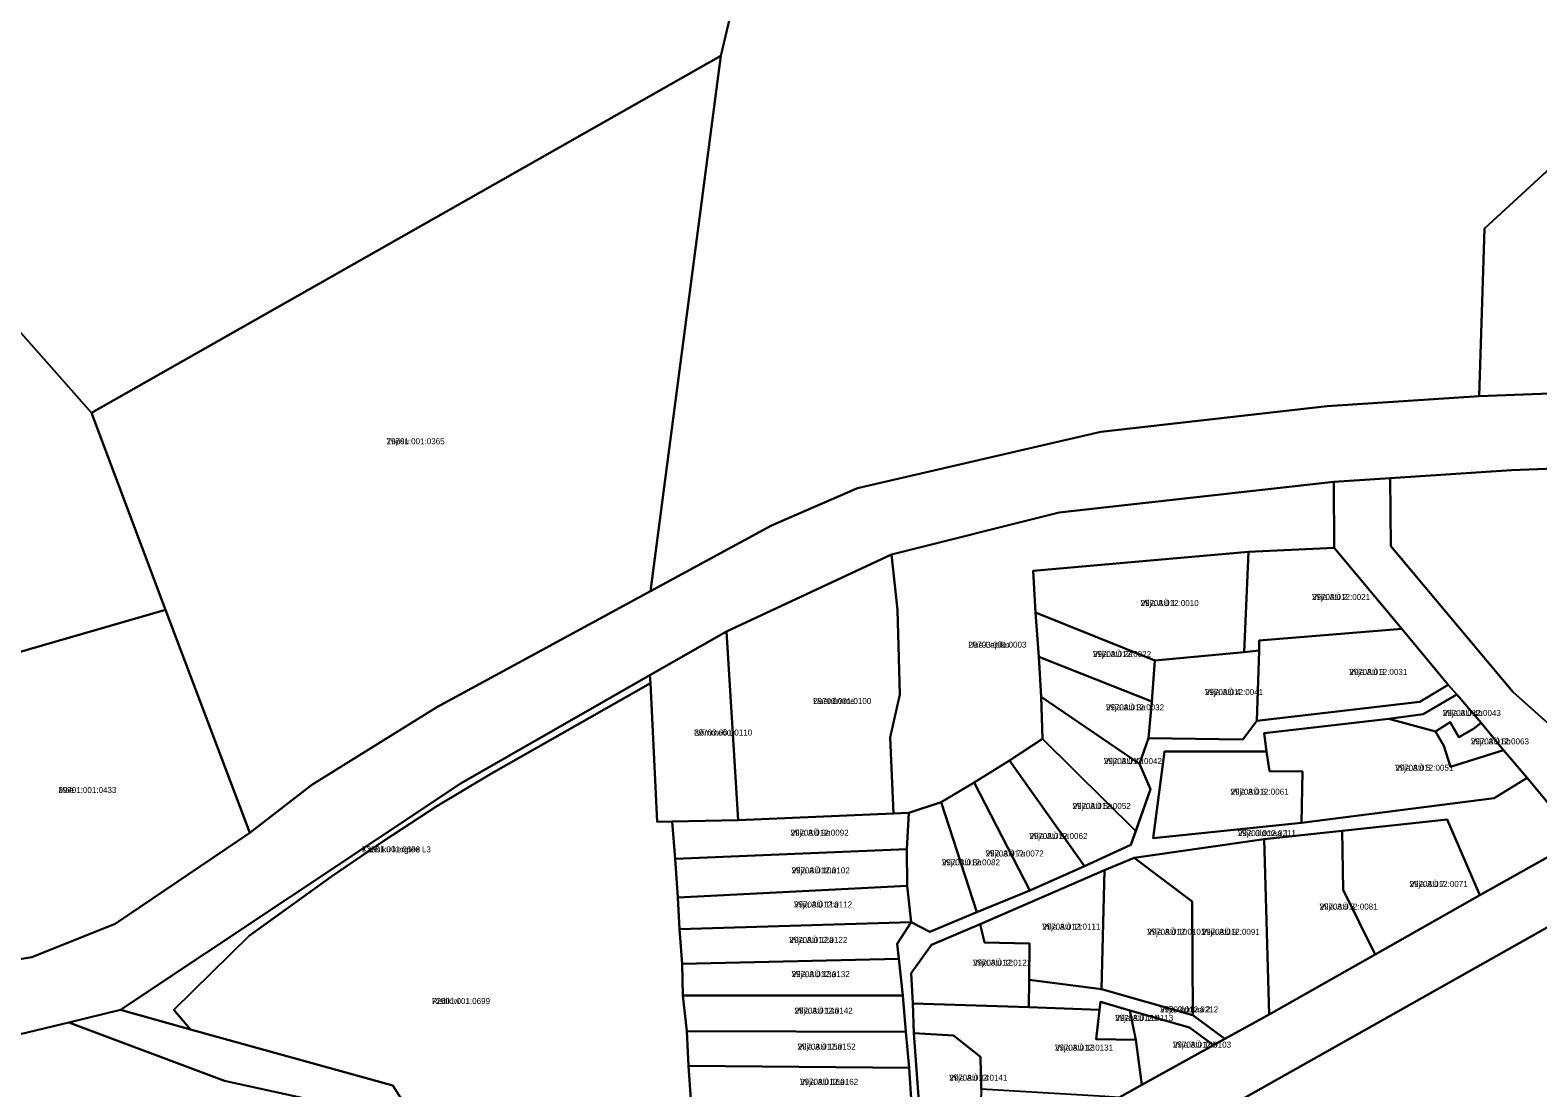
# Model space of a CAD drawing. Extents: x 504287 to 537970, y 6539941 to 6586214.
# Drawn here: x 518594.6 to 518970.8, y 6562077.4 to 6562341.2 of the extents above; entities that cross this region are included whole.
import ezdxf

# ---------------------------------------------------------------- set-up
doc = ezdxf.new("R2010")
doc.units = 0
for name, color, linetype in [('L_AADRESS', 7, 'Continuous'), ('PIIR', 7, 'Continuous'), ('TUNNUS', 7, 'Continuous')]:
    doc.layers.add(name, color=color, linetype=linetype)

msp = doc.modelspace()

# ---------------------------------------------------------------- linework, layer by layer
at = {"layer": 'PIIR'}
for points in [[(518475.75, 6562758.01), (518677.1, 6562981.81), (518635.19, 6562690.91), (518826.94, 6562587.62), (518766.99, 6562334.8), (518609.92, 6562245.71), (518524.03, 6562342.9), (518469.95, 6562404.01), (518435.56, 6562442.92), (518449.9, 6562487.21), (518389.7, 6562505.8), (518316.62, 6562566.33)], [(518766.99, 6562334.8), (518749.42, 6562201.27), (518696.14, 6562172.35), (518664.92, 6562152.99), (518649.43, 6562140.98), (518628.39, 6562196.62), (518609.92, 6562245.71)], [(518991.5, 6562322.94), (519036.8, 6562302.12), (519020.18, 6562252.3), (518956.2, 6562249.85), (518957.55, 6562291.71)], [(518933.96, 6562229.44), (518964.27, 6562231.47), (519024.63, 6562233.72), (519022.07, 6562169.2), (518984.95, 6562157.97), (518964.56, 6562176.11), (518934.17, 6562212.46)], [(518919.99, 6562212.04), (518898.62, 6562211.09), (518844.91, 6562206.29), (518845.46, 6562195.91), (518846.34, 6562184.88), (518846.86, 6562174.89), (518847.25, 6562164.44), (518838.96, 6562159.05), (518830.2, 6562153.55), (518821.98, 6562148.63), (518813.91, 6562145.98), (518810.05, 6562145.81), (518809.18, 6562164.75), (518811.64, 6562175.46), (518811.01, 6562196.57), (518809.58, 6562210.38), (518851.41, 6562220.9), (518919.96, 6562228.5)], [(518845.46, 6562195.91), (518844.91, 6562206.29), (518898.62, 6562211.09), (518897.52, 6562186.06), (518875.27, 6562183.98)], [(518901.28, 6562186.44), (518897.52, 6562186.06), (518898.62, 6562211.09), (518919.99, 6562212.04), (518936.93, 6562191.82), (518901.32, 6562188.99)], [(518811.01, 6562196.57), (518811.64, 6562175.46), (518809.18, 6562164.75), (518810.05, 6562145.81), (518771.31, 6562144.14), (518768.38, 6562191.22), (518809.58, 6562210.38)], [(518566.68, 6562105.2), (518552.93, 6562174.78), (518628.39, 6562196.62), (518649.43, 6562140.98), (518615.87, 6562118.26), (518595.02, 6562109.94)], [(518845.46, 6562195.91), (518875.27, 6562183.98), (518874.52, 6562173.73), (518846.34, 6562184.88)], [(518771.31, 6562144.14), (518754.86, 6562143.79), (518751.09, 6562143.74), (518749.4, 6562178.27), (518749.29, 6562180.29), (518768.38, 6562191.22)], [(518901.28, 6562186.44), (518901.32, 6562188.99), (518936.93, 6562191.82), (518948.45, 6562177.91), (518941.35, 6562173.64), (518900.72, 6562168.91)], [(518846.34, 6562184.88), (518874.52, 6562173.73), (518873.68, 6562164.6), (518871.43, 6562158.17), (518846.86, 6562174.89)], [(518874.52, 6562173.73), (518875.27, 6562183.98), (518897.52, 6562186.06), (518901.28, 6562186.44), (518900.72, 6562168.91), (518897.21, 6562164.22), (518873.68, 6562164.6)], [(518634.67, 6562091.94), (518617.21, 6562096.8), (518702.16, 6562153.36), (518749.29, 6562180.29), (518749.4, 6562178.27), (518709.77, 6562155.75), (518696.13, 6562147.63), (518682.85, 6562138.99), (518669.79, 6562130.13), (518649.28, 6562115.28), (518630.51, 6562096.8)], [(518846.86, 6562174.89), (518871.43, 6562158.17), (518874.2, 6562151.83), (518870.52, 6562141.37), (518847.25, 6562164.44)], [(518933.67, 6562169.42), (518942.21, 6562170.56), (518950.6, 6562175.47), (518956.7, 6562168.4), (518954.81, 6562166.94), (518951.1, 6562164.8), (518948.91, 6562168.62), (518945.32, 6562166.26)], [(518912.14, 6562156.29), (518903.88, 6562156.4), (518903.16, 6562161.28), (518902.55, 6562165.87), (518933.67, 6562169.42), (518945.32, 6562166.26), (518947.37, 6562162.71), (518949.05, 6562157.47), (518962.24, 6562161.56), (518968.14, 6562154.66), (518959.89, 6562149.65), (518911.86, 6562143.5)], [(518947.37, 6562162.71), (518945.32, 6562166.26), (518948.91, 6562168.62), (518951.1, 6562164.8), (518954.81, 6562166.94), (518956.7, 6562168.4), (518962.24, 6562161.56), (518949.05, 6562157.47)], [(518847.25, 6562164.44), (518870.52, 6562141.37), (518869.28, 6562137.99), (518857.68, 6562132.7), (518838.96, 6562159.05)], [(518830.2, 6562153.55), (518838.96, 6562159.05), (518857.68, 6562132.7), (518844.08, 6562126.56)], [(518877.68, 6562161.25), (518903.16, 6562161.28), (518903.88, 6562156.4), (518912.14, 6562156.29), (518911.86, 6562143.5), (518874.87, 6562139.68)], [(518821.98, 6562148.63), (518830.2, 6562153.55), (518844.08, 6562126.56), (518830.84, 6562121.22)], [(518814.48, 6562118.73), (518813.49, 6562127.78), (518813.41, 6562136.9), (518813.91, 6562145.98), (518821.98, 6562148.63), (518830.84, 6562121.22), (518819.1, 6562116.28)], [(518813.91, 6562145.98), (518813.41, 6562136.9), (518755.53, 6562134.53), (518754.86, 6562143.79), (518771.31, 6562144.14), (518810.05, 6562145.81)], [(518922.24, 6562126.75), (518922.01, 6562141.47), (518948.22, 6562144.3), (518956.32, 6562125.43), (518930.22, 6562110.67)], [(518884.78, 6562095.5), (518884.6, 6562123.84), (518870.14, 6562134.78), (518902.5, 6562139.4), (518903.75, 6562095.65), (518892.74, 6562089.63)], [(518902.5, 6562139.4), (518922.01, 6562141.47), (518922.24, 6562126.75), (518930.22, 6562110.67), (518903.75, 6562095.65)], [(518755.53, 6562134.53), (518813.41, 6562136.9), (518813.49, 6562127.78), (518756.24, 6562124.83)], [(518844.21, 6562011.8), (518836.84, 6562012.6), (518844.21, 6562037.85), (518845.16, 6562041.36), (518846.09, 6562044.48), (518861.89, 6562072.25), (518862.8, 6562075.26), (518866.38, 6562074.95), (518871.99, 6562078.13), (518889.92, 6562088.02), (518892.74, 6562089.63), (518903.75, 6562095.65), (518930.22, 6562110.67), (518956.32, 6562125.43), (518980.97, 6562139.21), (518990.73, 6562127.26), (518881.96, 6562066.06), (518860.8, 6562045.82), (518853.6, 6562034.04)], [(518862.74, 6562131.66), (518870.14, 6562134.78), (518884.6, 6562123.84), (518884.78, 6562095.5), (518861.94, 6562102.02)], [(518843.95, 6562113.38), (518832.76, 6562113.61), (518831.67, 6562118.23), (518862.74, 6562131.66), (518861.94, 6562102.02), (518843.94, 6562104.34)], [(518756.24, 6562124.83), (518813.49, 6562127.78), (518814.48, 6562118.73), (518756.68, 6562116.93)], [(518882.09, 6561992.35), (518844.21, 6562011.8), (518853.6, 6562034.04), (518860.8, 6562045.82), (518881.96, 6562066.06), (518990.73, 6562127.26), (519021.61, 6562068.59), (518984.83, 6562046.85), (518949.38, 6562025.42), (518930.25, 6562014.02), (518911.77, 6562003.1), (518908.77, 6562008.3)], [(518756.68, 6562116.93), (518814.48, 6562118.73), (518810.96, 6562113.31), (518811.34, 6562109.58), (518757.31, 6562108.33)], [(518814.5, 6562105.99), (518819.51, 6562113.03), (518831.67, 6562118.23), (518832.76, 6562113.61), (518843.95, 6562113.38), (518843.94, 6562104.34), (518843.81, 6562097.48), (518814.9, 6562098.4)], [(518757.31, 6562108.33), (518811.34, 6562109.58), (518812.4, 6562100.41), (518757.52, 6562100.43)], [(518843.94, 6562104.34), (518861.94, 6562102.02), (518884.78, 6562095.5), (518892.74, 6562089.63), (518889.92, 6562088.02), (518883.92, 6562092.44), (518869.02, 6562096.66), (518861.69, 6562098.84), (518861.48, 6562096.87), (518843.81, 6562097.48)], [(518757.52, 6562100.43), (518812.4, 6562100.41), (518813.1, 6562091.32), (518758.46, 6562091.52)], [(518831.8, 6562085.15), (518825, 6562090.41), (518815.14, 6562091.02), (518814.9, 6562098.4), (518843.81, 6562097.48), (518861.48, 6562096.87), (518860.61, 6562089.55), (518870.51, 6562089.33), (518871.99, 6562078.13), (518866.38, 6562074.95), (518862.8, 6562075.26), (518831.94, 6562077.04)], [(518861.48, 6562096.87), (518861.69, 6562098.84), (518869.02, 6562096.66), (518870.51, 6562089.33), (518860.61, 6562089.55)], [(518870.51, 6562089.33), (518869.02, 6562096.66), (518883.92, 6562092.44), (518889.92, 6562088.02), (518871.99, 6562078.13)], [(518643.09, 6562079.14), (518676.15, 6562071.9), (518676.82, 6561797.25), (518631.02, 6561816.34), (518629.22, 6561817.09), (518537.2, 6561858.42), (518545.01, 6561888.17), (518554.72, 6561923.51), (518519.2, 6561922.14), (518469.34, 6561919.09), (518472.12, 6561926.87), (518556.08, 6562085.74), (518577.49, 6562087.27), (518604.29, 6562093.69)], [(518758.46, 6562091.52), (518813.1, 6562091.32), (518814, 6562082.33), (518758.89, 6562082.9)], [(518815.14, 6562091.02), (518825, 6562090.41), (518831.8, 6562085.15), (518831.94, 6562077.04), (518831.85, 6562073.82), (518861.89, 6562072.25), (518853.23, 6562067.33), (518816.66, 6562070.63)], [(518759.51, 6562074.58), (518758.89, 6562082.9), (518814, 6562082.33), (518814.51, 6562073.37)]]:
    msp.add_lwpolyline(points, close=True, dxfattribs=at)
for points in [[(519354.1, 6562777.58), (518991.5, 6562322.94), (518957.55, 6562291.71), (518956.2, 6562249.85), (518918.29, 6562247.42), (518861.76, 6562241), (518801.03, 6562226.96), (518779.6, 6562217.63), (518749.42, 6562201.27), (518766.99, 6562334.8), (518826.94, 6562587.62)], [(518207.35, 6562413.84), (518257.69, 6562495.23), (518422.52, 6562457.55), (518435.56, 6562442.92), (518469.95, 6562404.01), (518427.57, 6562222.45), (518498.13, 6562231.74), (518524.03, 6562342.9), (518609.92, 6562245.71), (518628.39, 6562196.62), (518552.93, 6562174.78), (518488.36, 6562156.01), (518362.48, 6562148.68), (518356.06, 6562086.39), (518343.83, 6562086.7), (518343.82, 6562090.13), (518332.95, 6562090.41), (518334.78, 6562134.39), (518277.98, 6562164.81), (518251.89, 6562177.79), (518220.42, 6562192.89)], [(518566.68, 6562105.2), (518595.02, 6562109.94), (518615.87, 6562118.26), (518649.43, 6562140.98), (518664.92, 6562152.99), (518696.14, 6562172.35), (518749.42, 6562201.27), (518779.6, 6562217.63), (518801.03, 6562226.96), (518861.76, 6562241), (518918.29, 6562247.42), (518956.2, 6562249.85), (519020.18, 6562252.3), (519120.43, 6562250.63), (519226.17, 6562256.12), (519357.09, 6562234.09)], [(519265.7, 6562230.41), (519223.24, 6562237.31), (519117.52, 6562231.81), (519024.63, 6562233.72), (518964.27, 6562231.47), (518933.96, 6562229.44), (518919.96, 6562228.5), (518851.41, 6562220.9), (518809.58, 6562210.38), (518768.38, 6562191.22), (518749.29, 6562180.29), (518702.16, 6562153.36), (518617.21, 6562096.8), (518604.29, 6562093.69), (518577.49, 6562087.27)], [(518980.97, 6562139.21), (518968.14, 6562154.66), (518962.24, 6562161.56), (518956.7, 6562168.4), (518950.6, 6562175.47), (518948.45, 6562177.91), (518936.93, 6562191.82), (518919.99, 6562212.04), (518919.96, 6562228.5), (518933.96, 6562229.44), (518934.17, 6562212.46), (518964.56, 6562176.11), (518984.95, 6562157.97)], [(518710.65, 6562037.64), (518685.15, 6562077.97), (518634.67, 6562091.94), (518630.51, 6562096.8), (518649.28, 6562115.28), (518669.79, 6562130.13), (518682.85, 6562138.99), (518696.13, 6562147.63), (518709.77, 6562155.75), (518749.4, 6562178.27), (518751.09, 6562143.74), (518754.86, 6562143.79), (518755.53, 6562134.53), (518756.24, 6562124.83), (518756.68, 6562116.93), (518757.31, 6562108.33), (518757.52, 6562100.43), (518758.46, 6562091.52), (518758.89, 6562082.9), (518759.51, 6562074.58)], [(518814.51, 6562073.37), (518814, 6562082.33), (518813.1, 6562091.32), (518812.4, 6562100.41), (518811.34, 6562109.58), (518810.96, 6562113.31), (518814.48, 6562118.73), (518819.1, 6562116.28), (518830.84, 6562121.22), (518844.08, 6562126.56), (518857.68, 6562132.7), (518869.28, 6562137.99), (518874.2, 6562151.83), (518871.43, 6562158.17), (518873.68, 6562164.6), (518897.21, 6562164.22), (518900.72, 6562168.91), (518941.35, 6562173.64), (518948.45, 6562177.91), (518950.6, 6562175.47), (518942.21, 6562170.56), (518933.67, 6562169.42), (518902.55, 6562165.87), (518903.16, 6562161.28), (518877.68, 6562161.25), (518874.87, 6562139.68), (518911.86, 6562143.5), (518959.89, 6562149.65), (518968.14, 6562154.66), (518980.97, 6562139.21), (518956.32, 6562125.43), (518948.22, 6562144.3), (518922.01, 6562141.47), (518902.5, 6562139.4), (518870.14, 6562134.78), (518862.74, 6562131.66), (518831.67, 6562118.23), (518819.51, 6562113.03), (518814.5, 6562105.99), (518814.9, 6562098.4), (518815.14, 6562091.02), (518816.66, 6562070.63)], [(518676.15, 6562071.9), (518643.09, 6562079.14), (518604.29, 6562093.69), (518617.21, 6562096.8), (518634.67, 6562091.94), (518685.15, 6562077.97), (518710.65, 6562037.64)]]:
    msp.add_lwpolyline(points, dxfattribs=at)

# ---------------------------------------------------------------- texts
at = {"layer": 'L_AADRESS'}
for s, p in [('Topsu', (518683.55, 6562237.89)), ('Vilja AÜ 2', (518914.48, 6562199.05)), ('Vilja AÜ 1', (518871.7, 6562197.54)), ('Uue-Lepiku', (518828.72, 6562187.15)), ('Vilja AÜ 2a', (518859.83, 6562184.82)), ('Vilja AÜ 3', (518923.75, 6562180.37)), ('Vilja AÜ 4', (518887.78, 6562175.33)), ('Uuenõmme', (518790.01, 6562173.11)), ('Vilja AÜ 3a', (518863.06, 6562171.53)), ('Vilja AÜ 4b', (518947.11, 6562170.13)), ('Nõmmeõue', (518760.3, 6562165.25)), ('Vilja AÜ 6b', (518954.11, 6562163.04)), ('Vilja AÜ 4a', (518862.53, 6562158.13)), ('Vilja AÜ 5', (518935.24, 6562156.46)), ('Mäe', (518601.66, 6562150.91)), ('Vilja AÜ 6', (518894.14, 6562150.48)), ('Vilja AÜ 5a', (518854.74, 6562146.93)), ('Vilja AÜ 9a', (518784.36, 6562140.26)), ('Vilja AÜ 6a', (518843.94, 6562139.44)), ('Vilja üldmaa 1', (518895.96, 6562140.16)), ('Kaasiku kergtee L3', (518677.44, 6562136.12)), ('Vilja AÜ 7a', (518833.03, 6562135.08)), ('Vilja AÜ 10a', (518784.63, 6562130.86)), ('Vilja AÜ 8a', (518822.12, 6562132.87)), ('Vilja AÜ 7', (518938.83, 6562127.49)), ('Vilja AÜ 11a', (518785.23, 6562122.36)), ('Vilja AÜ 8', (518916.36, 6562121.84)), ('Vilja AÜ 11', (518847.17, 6562116.84)), ('Vilja AÜ 10', (518873.36, 6562115.55)), ('Vilja AÜ 9', (518886.95, 6562115.54)), ('Vilja AÜ 12a', (518784.02, 6562113.53)), ('Vilja AÜ 12', (518829.89, 6562107.86)), ('Vilja AÜ 13a', (518784.63, 6562104.99)), ('Ristikivi', (518694.88, 6562098.28)), ('Vilja AÜ 14a', (518785.37, 6562095.88)), ('Vilja AÜ 11b', (518865.35, 6562094.08)), ('Vilja üldmaa 2', (518876.56, 6562096.18)), ('Vilja AÜ 15a', (518786.11, 6562086.92)), ('Vilja AÜ 13', (518850.34, 6562086.67)), ('Vilja AÜ 10b', (518879.78, 6562087.4)), ('Vilja AÜ 16a', (518786.74, 6562078.13)), ('Vilja AÜ 14', (518823.96, 6562079.17))]:
    msp.add_text(s, height=1.5, dxfattribs=at).set_placement(p)
at = {"layer": 'TUNNUS'}
for s, p in [('29701:001:0365', (518683.55, 6562237.89)), ('29703:012:0021', (518914.48, 6562199.05)), ('29703:012:0010', (518871.7, 6562197.54)), ('29703:001:0003', (518828.72, 6562187.15)), ('29703:012:0022', (518859.83, 6562184.82)), ('29703:012:0031', (518923.75, 6562180.37)), ('29703:001:0100', (518790.01, 6562173.11)), ('29703:012:0041', (518887.78, 6562175.33)), ('29703:012:0032', (518863.06, 6562171.53)), ('29703:012:0043', (518947.11, 6562170.13)), ('29703:001:0110', (518760.3, 6562165.25)), ('29703:012:0063', (518954.11, 6562163.04)), ('29703:012:0042', (518862.53, 6562158.13)), ('29703:012:0051', (518935.24, 6562156.46)), ('29701:001:0433', (518601.66, 6562150.91)), ('29703:012:0061', (518894.14, 6562150.48)), ('29703:012:0052', (518854.74, 6562146.93)), ('29703:012:0092', (518784.36, 6562140.26)), ('29703:012:0062', (518843.94, 6562139.44)), ('29703:012:0211', (518895.96, 6562140.16)), ('72501:001:0698', (518677.44, 6562136.12)), ('29703:012:0072', (518833.03, 6562135.08)), ('29703:012:0102', (518784.63, 6562130.86)), ('29703:012:0082', (518822.12, 6562132.87)), ('29703:012:0071', (518938.83, 6562127.49)), ('29703:012:0112', (518785.23, 6562122.36)), ('29703:012:0081', (518916.36, 6562121.84)), ('29703:012:0111', (518847.17, 6562116.84)), ('29703:012:0101', (518873.36, 6562115.55)), ('29703:012:0091', (518886.95, 6562115.54)), ('29703:012:0122', (518784.02, 6562113.53)), ('29703:012:0121', (518829.89, 6562107.86)), ('29703:012:0132', (518784.63, 6562104.99)), ('72501:001:0699', (518694.88, 6562098.28)), ('29703:012:0142', (518785.37, 6562095.88)), ('29703:012:0113', (518865.35, 6562094.08)), ('29703:012:0212', (518876.56, 6562096.18)), ('29703:012:0152', (518786.11, 6562086.92)), ('29703:012:0131', (518850.34, 6562086.67)), ('29703:012:0103', (518879.78, 6562087.4)), ('29703:012:0162', (518786.74, 6562078.13)), ('29703:012:0141', (518823.96, 6562079.17))]:
    msp.add_text(s, height=1.5, dxfattribs=at).set_placement(p)

doc.saveas('drawing.dxf')
